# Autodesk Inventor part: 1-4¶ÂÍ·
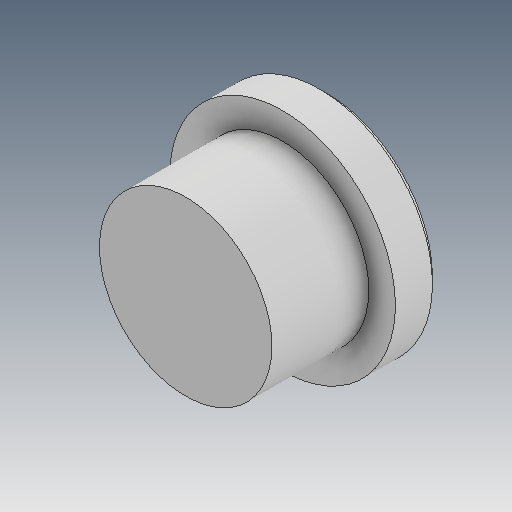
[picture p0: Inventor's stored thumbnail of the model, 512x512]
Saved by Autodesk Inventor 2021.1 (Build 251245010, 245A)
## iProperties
Created: 2019-04
Part Number: 1-4¶ÂÍ·
Material: Ogólny
Document SubType Name: Modeling
Designer: user
Density: 1 g/cm^3
Appearance: Domyślna
Author: user
Revision Number: ÈÎºÎ
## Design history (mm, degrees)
feature "µ¹½Ç2"
node "Bryła1"
